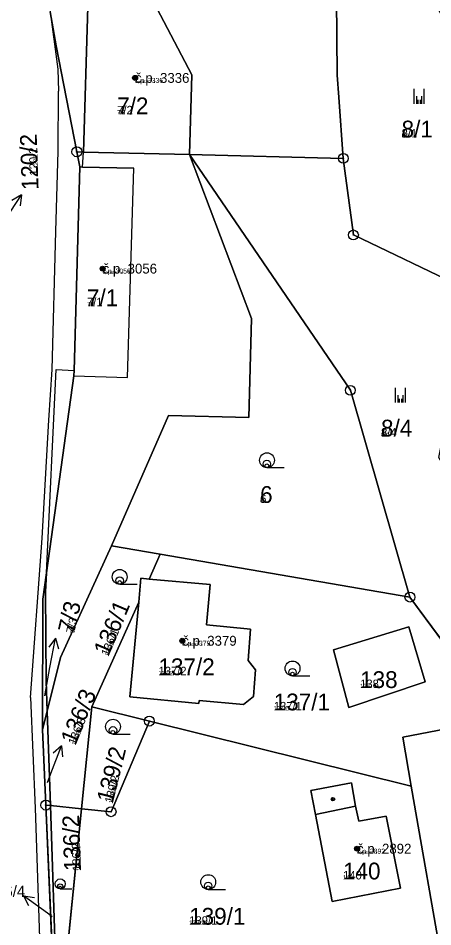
# Model space of a CAD drawing. Extents: x -759873 to -758487, y -975024 to -973516.
# Drawn here: x -759297.9 to -759256, y -974428.7 to -974336.8 of the extents above; entities that cross this region are included whole.
import ezdxf

# ---------------------------------------------------------------- set-up
doc = ezdxf.new("R2010")
doc.units = 0
for name, color, linetype in [('KAT_02_hranice parcel', 7, 'Continuous'), ('KAT_03_1000_st čísla parcelní', 7, 'Continuous'), ('KAT_03_1000_čísla parcelní', 7, 'Continuous'), ('KAT_03_1000_čísla popisná', 7, 'Continuous'), ('KAT_03_250_st čísla parcelní', 7, 'Continuous'), ('KAT_03_250_čísla parcelní', 7, 'Continuous'), ('KAT_03_250_čísla popisná', 7, 'Continuous'), ('KAT_03_500_st čísla parcelní', 7, 'Continuous'), ('KAT_03_500_čísla parcelní', 7, 'Continuous'), ('KAT_03_500_čísla popisná', 7, 'Continuous'), ('KAT_04_vnitřní kresba', 7, 'Continuous'), ('KAT_05_1000_značky kultur', 7, 'Continuous'), ('KAT_05_250_značky kultur', 7, 'Continuous'), ('KAT_05_500_značky kultur', 7, 'Continuous'), ('KAT_07_1000_značky budov', 7, 'Continuous'), ('KAT_07_250_značky budov', 7, 'Continuous'), ('KAT_07_500_značky budov', 7, 'Continuous'), ('KAT_11_značky bodu BP', 7, 'Continuous'), ('KAT_12_pomocná šipka', 7, 'Continuous'), ('KAT_14_plocha_budovy', 7, 'Continuous'), ('KAT_14_plocha_pozemek', 7, 'Continuous')]:
    doc.layers.add(name, color=color, linetype=linetype)

msp = doc.modelspace()

# ---------------------------------------------------------------- linework, layer by layer
at = {"layer": 'KAT_02_hranice parcel'}
for p, q in [((-759280.6, -974350.56), (-759265.03, -974350.94)), ((-759288.51, -974390.16), (-759283.57, -974391)), ((-759284.69, -974393.51), (-759283.57, -974391)), ((-759283.57, -974391), (-759258.29, -974395.34)), ((-759290.48, -974406.44), (-759285.74, -974395.86)), ((-759258.29, -974395.34), (-759252.87, -974402.7)), ((-759295.47, -974408.74), (-759295.01, -974406.87)), ((-759295.01, -974406.87), (-759294.68, -974416.44)), ((-759291.52, -974416.76), (-759290.48, -974406.44)), ((-759290.48, -974406.44), (-759284.66, -974407.89)), ((-759284.66, -974407.89), (-759258.17, -974414.46)), ((-759295.47, -974408.74), (-759295.14, -974416.39)), ((-759254.9, -974433.16), (-759258.17, -974414.46)), ((-759295.14, -974416.39), (-759294.12, -974439.78)), ((-759295.14, -974416.39), (-759294.68, -974416.44)), ((-759294.68, -974416.44), (-759291.52, -974416.76)), ((-759294.04, -974441.63), (-759291.52, -974416.76))]:
    msp.add_line(p, q, dxfattribs=at)
for points in [[(-759265.74, -974330.84), (-759265.67, -974342.52), (-759265.5, -974344.74), (-759265.03, -974350.94)], [(-759294.88, -974335.08), (-759294.7, -974336.11), (-759294.1, -974339.54), (-759292, -974350.28)], [(-759280.6, -974350.56), (-759280.36, -974342.49), (-759284.25, -974335.11), (-759290.88, -974335.09), (-759294.88, -974335.08)], [(-759292, -974350.28), (-759291.7, -974351.8), (-759292.28, -974372.4), (-759292.3, -974372.96), (-759295.07, -974392.89)], [(-759280.6, -974350.56), (-759291.33, -974350.3), (-759292, -974350.28)], [(-759280.6, -974350.56), (-759274.34, -974367.15), (-759274.6, -974377.18), (-759282.74, -974376.97), (-759288.51, -974390.16)], [(-759258.29, -974395.34), (-759264.32, -974374.41), (-759280.6, -974350.56)], [(-759265.03, -974350.94), (-759264.01, -974358.69), (-759252.89, -974364.02), (-759252.04, -974364.43)], [(-759295.01, -974406.87), (-759293.67, -974401.46), (-759288.51, -974390.16)], [(-759295.07, -974392.89), (-759295.44, -974395.56), (-759295.47, -974408.74)], [(-759295.07, -974392.89), (-759295.16, -974394.79), (-759295.11, -974403.85), (-759295.01, -974406.87)], [(-759284.69, -974393.51), (-759278.51, -974394.07), (-759278.88, -974398.14), (-759274.42, -974398.6), (-759274.67, -974401.75), (-759273.92, -974402.69), (-759274.11, -974405.39), (-759275.14, -974406.22), (-759279.61, -974405.79), (-759279.64, -974406.09), (-759286.64, -974405.44), (-759285.74, -974395.86)], [(-759285.74, -974395.86), (-759285.52, -974393.43), (-759284.69, -974393.51)], [(-759256.73, -974403.91), (-759264.47, -974406.51), (-759266.02, -974400.69), (-759258.4, -974398.34), (-759256.73, -974403.91)], [(-759258.17, -974414.46), (-759259, -974409.5), (-759253.74, -974408.5), (-759252.87, -974402.7)], [(-759284.66, -974407.89), (-759288.54, -974417.06), (-759291.52, -974416.76)], [(-759263.81, -974416.51), (-759263.46, -974418.01), (-759260.68, -974417.5), (-759259.23, -974424.81), (-759266.15, -974426.14), (-759267.84, -974417.34), (-759268.31, -974414.91), (-759264.21, -974414.13), (-759263.81, -974416.51)], [(-759294.68, -974416.44), (-759294.09, -974434.05), (-759294.06, -974439.07), (-759294.12, -974439.78)]]:
    msp.add_lwpolyline(points, dxfattribs=at)
at = {"layer": 'KAT_03_1000_čísla popisná'}
for centre in [(-759286.11, -974342.8), (-759289.39, -974362.1), (-759281.33, -974399.76), (-759263.64, -974420.8)]:
    msp.add_circle(centre, 0.25, dxfattribs=at)
at = {"layer": 'KAT_03_250_čísla popisná'}
for centre in [(-759286.11, -974342.8), (-759289.39, -974362.1), (-759281.33, -974399.76), (-759263.64, -974420.8)]:
    msp.add_circle(centre, 0.0625, dxfattribs=at)
at = {"layer": 'KAT_03_500_čísla popisná'}
for centre in [(-759286.11, -974342.8), (-759289.39, -974362.1), (-759281.33, -974399.76), (-759263.64, -974420.8)]:
    msp.add_circle(centre, 0.125, dxfattribs=at)
at = {"layer": 'KAT_04_vnitřní kresba'}
for p, q in [((-759294.7, -974336.11), (-759293.94, -974341.92)), ((-759291.33, -974350.3), (-759290.9, -974335.62)), ((-759293.94, -974341.92), (-759293.86, -974344.13)), ((-759293.89, -974350.2), (-759293.86, -974344.13)), ((-759294.13, -974358.35), (-759293.89, -974350.2)), ((-759291.44, -974351.83), (-759291.33, -974350.3)), ((-759291.7, -974351.8), (-759291.44, -974351.83)), ((-759291.44, -974351.83), (-759286.25, -974351.95)), ((-759286.88, -974373.11), (-759286.25, -974351.95)), ((-759294.49, -974372.3), (-759294.13, -974358.35)), ((-759295.07, -974392.89), (-759294.08, -974372.3)), ((-759294.83, -974377.45), (-759294.49, -974372.3)), ((-759294.08, -974372.3), (-759292.28, -974372.4)), ((-759292.3, -974372.96), (-759286.88, -974373.11)), ((-759295.5, -974389.38), (-759294.83, -974377.45)), ((-759296.68, -974405.49), (-759295.5, -974389.38)), ((-759296.68, -974405.49), (-759296.21, -974416.7)), ((-759296.21, -974416.7), (-759295.62, -974435.22)), ((-759267.84, -974417.34), (-759263.81, -974416.51))]:
    msp.add_line(p, q, dxfattribs=at)
at = {"layer": 'KAT_05_1000_značky kultur'}
for p, q in [((-759257.851, -974345.41), (-759257.851, -974343.91)), ((-759256.85, -974345.41), (-759256.85, -974343.91)), ((-759259.741, -974375.66), (-759259.741, -974374.16)), ((-759258.74, -974375.66), (-759258.74, -974374.16)), ((-759272.763, -974382.24), (-759271.013, -974382.24)), ((-759287.663, -974394.04), (-759285.913, -974394.04)), ((-759270.173, -974403.31), (-759268.423, -974403.31)), ((-759288.343, -974409.2), (-759286.593, -974409.2)), ((-759293.685, -974424.86), (-759292.513, -974424.86)), ((-759278.703, -974424.93), (-759276.953, -974424.93))]:
    msp.add_line(p, q, dxfattribs=at)
for centre, radius in [((-759272.763, -974381.49), 0.75), ((-759287.663, -974393.29), 0.75), ((-759270.173, -974402.56), 0.75), ((-759288.343, -974408.45), 0.75), ((-759278.703, -974424.18), 0.75), ((-759293.685, -974424.357), 0.502)]:
    msp.add_circle(centre, radius, dxfattribs=at)
at = {"layer": 'KAT_05_250_značky kultur'}
for p, q in [((-759257.468, -974345.41), (-759257.468, -974345.035)), ((-759257.218, -974345.41), (-759257.218, -974345.035)), ((-759259.358, -974375.66), (-759259.358, -974375.285)), ((-759259.108, -974375.66), (-759259.108, -974375.285)), ((-759272.768, -974382.24), (-759272.331, -974382.24)), ((-759287.668, -974394.04), (-759287.231, -974394.04)), ((-759270.178, -974403.31), (-759269.741, -974403.31)), ((-759288.348, -974409.2), (-759287.911, -974409.2)), ((-759293.689, -974424.86), (-759293.396, -974424.86)), ((-759278.708, -974424.93), (-759278.271, -974424.93))]:
    msp.add_line(p, q, dxfattribs=at)
for centre, radius in [((-759272.768, -974382.052), 0.187), ((-759287.668, -974393.852), 0.187), ((-759270.178, -974403.122), 0.187), ((-759288.348, -974409.012), 0.187), ((-759293.689, -974424.734), 0.126), ((-759278.708, -974424.742), 0.187)]:
    msp.add_circle(centre, radius, dxfattribs=at)
at = {"layer": 'KAT_05_500_značky kultur'}
for p, q in [((-759257.596, -974345.41), (-759257.596, -974344.66)), ((-759257.095, -974345.41), (-759257.095, -974344.66)), ((-759259.486, -974375.66), (-759259.486, -974374.91)), ((-759258.985, -974375.66), (-759258.985, -974374.91)), ((-759272.767, -974382.24), (-759271.892, -974382.24)), ((-759287.667, -974394.04), (-759286.792, -974394.04)), ((-759270.177, -974403.31), (-759269.302, -974403.31)), ((-759288.346, -974409.2), (-759287.471, -974409.2)), ((-759293.688, -974424.86), (-759293.101, -974424.86)), ((-759278.706, -974424.93), (-759277.831, -974424.93))]:
    msp.add_line(p, q, dxfattribs=at)
for centre, radius in [((-759272.766, -974381.865), 0.375), ((-759287.666, -974393.665), 0.375), ((-759270.176, -974402.935), 0.375), ((-759288.346, -974408.825), 0.375), ((-759293.688, -974424.609), 0.251), ((-759278.706, -974424.555), 0.375)]:
    msp.add_circle(centre, radius, dxfattribs=at)
at = {"layer": 'KAT_07_1000_značky budov'}
for centre in [(-759286.117, -974342.799), (-759289.397, -974362.099), (-759281.337, -974399.759), (-759266.077, -974415.789), (-759263.647, -974420.799)]:
    msp.add_circle(centre, 0.175, dxfattribs=at)
at = {"layer": 'KAT_07_250_značky budov'}
for centre in [(-759286.112, -974342.8), (-759289.392, -974362.1), (-759281.332, -974399.76), (-759266.072, -974415.79), (-759263.642, -974420.8)]:
    msp.add_circle(centre, 0.0437, dxfattribs=at)
at = {"layer": 'KAT_07_500_značky budov'}
for centre in [(-759286.113, -974342.8), (-759289.393, -974362.1), (-759281.333, -974399.76), (-759266.073, -974415.79), (-759263.643, -974420.8)]:
    msp.add_circle(centre, 0.0875, dxfattribs=at)
at = {"layer": 'KAT_11_značky bodu BP'}
for centre, radius in [((-759292, -974350.28), 0.5), ((-759292, -974350.28), 0.0303), ((-759265.03, -974350.94), 0.5), ((-759265.03, -974350.94), 0.0303), ((-759264.01, -974358.69), 0.5), ((-759264.01, -974358.69), 0.0303), ((-759264.32, -974374.41), 0.5), ((-759264.32, -974374.41), 0.0303), ((-759258.29, -974395.34), 0.5), ((-759258.29, -974395.34), 0.0303), ((-759284.66, -974407.89), 0.5), ((-759284.66, -974407.89), 0.0303), ((-759295.14, -974416.39), 0.5), ((-759295.14, -974416.39), 0.0303), ((-759288.54, -974417.06), 0.5), ((-759288.54, -974417.06), 0.0303)]:
    msp.add_circle(centre, radius, dxfattribs=at)
at = {"layer": 'KAT_12_pomocná šipka'}
for p, q in [((-759299.25, -974357.16), (-759297.616, -974354.643)), ((-759297.616, -974354.643), (-759298.581, -974355.21)), ((-759297.616, -974354.643), (-759297.741, -974355.756)), ((-759294.157, -974399.504), (-759294.84, -974400.392)), ((-759294.73, -974402.45), (-759294.157, -974399.504)), ((-759294.157, -974399.504), (-759293.857, -974400.583)), ((-759295.26, -974405.32), (-759294.73, -974402.45)), ((-759294.64, -974413.19), (-759293.565, -974410.388)), ((-759293.565, -974410.388), (-759294.391, -974411.144)), ((-759293.565, -974410.388), (-759293.456, -974411.503)), ((-759294.98, -974414.09), (-759294.64, -974413.19)), ((-759294.98, -974427.32), (-759297.408, -974425.556)), ((-759297.408, -974425.556), (-759296.303, -974425.74)), ((-759297.408, -974425.556), (-759296.892, -974426.55)), ((-759294.49, -974427.68), (-759294.98, -974427.32))]:
    msp.add_line(p, q, dxfattribs=at)
at = {"layer": 'KAT_14_plocha_budovy'}
for points in [[(-759280.6, -974350.56), (-759280.36, -974342.49), (-759284.25, -974335.11), (-759290.88, -974335.09), (-759290.9, -974335.62), (-759291.33, -974350.3)], [(-759292.3, -974372.96), (-759286.88, -974373.11), (-759286.25, -974351.95), (-759291.44, -974351.83), (-759291.7, -974351.8), (-759292.28, -974372.4)], [(-759279.64, -974406.09), (-759279.61, -974405.79), (-759275.14, -974406.22), (-759274.11, -974405.39), (-759273.92, -974402.69), (-759274.67, -974401.75), (-759274.42, -974398.6), (-759278.88, -974398.14), (-759278.51, -974394.07), (-759284.69, -974393.51), (-759285.52, -974393.43), (-759285.74, -974395.86), (-759286.64, -974405.44)], [(-759263.81, -974416.51), (-759267.84, -974417.34), (-759266.15, -974426.14), (-759259.23, -974424.81), (-759260.68, -974417.5), (-759263.46, -974418.01)]]:
    msp.add_lwpolyline(points, close=True, dxfattribs=at)
at = {"layer": 'KAT_14_plocha_pozemek'}
for points in [[(-759275.13, -974330.59), (-759276.47, -974329.86), (-759280.62, -974323.73), (-759282.44, -974321.04), (-759283.23, -974320.62), (-759297.93, -974312.94), (-759297.91, -974317.24), (-759297.5, -974320.18), (-759297.42, -974320.63), (-759294.88, -974335.08), (-759290.88, -974335.09), (-759284.25, -974335.11), (-759280.36, -974342.49), (-759280.6, -974350.56), (-759265.03, -974350.94), (-759265.5, -974344.74), (-759265.67, -974342.52), (-759265.74, -974330.84)], [(-759265.74, -974330.84), (-759265.67, -974342.52), (-759265.5, -974344.74), (-759265.03, -974350.94), (-759264.01, -974358.69), (-759252.89, -974364.02), (-759252.04, -974364.43), (-759251.38, -974361.09), (-759244.28, -974356.01), (-759262.85, -974322.33)], [(-759284.25, -974335.11), (-759290.88, -974335.09), (-759294.88, -974335.08), (-759294.7, -974336.11), (-759294.1, -974339.54), (-759292, -974350.28), (-759291.33, -974350.3), (-759280.6, -974350.56), (-759280.36, -974342.49)], [(-759295.11, -974403.85), (-759295.01, -974406.87), (-759293.67, -974401.46), (-759288.51, -974390.16), (-759282.74, -974376.97), (-759274.6, -974377.18), (-759274.34, -974367.15), (-759280.6, -974350.56), (-759291.33, -974350.3), (-759292, -974350.28), (-759291.7, -974351.8), (-759292.28, -974372.4), (-759292.3, -974372.96), (-759295.07, -974392.89), (-759295.16, -974394.79)], [(-759258.29, -974395.34), (-759264.32, -974374.41), (-759280.6, -974350.56), (-759274.34, -974367.15), (-759274.6, -974377.18), (-759282.74, -974376.97), (-759288.51, -974390.16), (-759283.57, -974391)], [(-759236.62, -974396.93), (-759245.48, -974393.46), (-759248.04, -974394.36), (-759249.25, -974391.99), (-759255.36, -974381.2), (-759252.04, -974364.43), (-759252.89, -974364.02), (-759264.01, -974358.69), (-759265.03, -974350.94), (-759280.6, -974350.56), (-759264.32, -974374.41), (-759258.29, -974395.34), (-759252.87, -974402.7), (-759249, -974402.07)], [(-759290.48, -974406.44), (-759285.74, -974395.86), (-759285.52, -974393.43), (-759284.69, -974393.51), (-759283.57, -974391), (-759288.51, -974390.16), (-759293.67, -974401.46), (-759295.01, -974406.87), (-759294.68, -974416.44), (-759291.52, -974416.76)], [(-759274.42, -974398.6), (-759274.67, -974401.75), (-759273.92, -974402.69), (-759274.11, -974405.39), (-759275.14, -974406.22), (-759279.61, -974405.79), (-759279.64, -974406.09), (-759286.64, -974405.44), (-759285.74, -974395.86), (-759290.48, -974406.44), (-759284.66, -974407.89), (-759258.17, -974414.46), (-759259, -974409.5), (-759253.74, -974408.5), (-759252.87, -974402.7), (-759258.29, -974395.34), (-759283.57, -974391), (-759284.69, -974393.51), (-759278.51, -974394.07), (-759278.88, -974398.14)], [(-759295.44, -974395.56), (-759295.47, -974408.74), (-759295.01, -974406.87), (-759295.11, -974403.85), (-759295.16, -974394.79), (-759295.07, -974392.89)], [(-759284.69, -974393.51), (-759285.52, -974393.43), (-759285.74, -974395.86), (-759286.64, -974405.44), (-759279.64, -974406.09), (-759279.61, -974405.79), (-759275.14, -974406.22), (-759274.11, -974405.39), (-759273.92, -974402.69), (-759274.67, -974401.75), (-759274.42, -974398.6), (-759278.88, -974398.14), (-759278.51, -974394.07)], [(-759256.73, -974403.91), (-759264.47, -974406.51), (-759266.02, -974400.69), (-759258.4, -974398.34)], [(-759256.73, -974403.91), (-759258.4, -974398.34), (-759266.02, -974400.69), (-759264.47, -974406.51)], [(-759246.94, -974406.33), (-759252.87, -974402.7), (-759253.74, -974408.5), (-759259, -974409.5), (-759258.17, -974414.46), (-759254.9, -974433.16), (-759243.31, -974423.49), (-759237.81, -974416.77), (-759240.16, -974413.72), (-759244.88, -974407.6), (-759245.61, -974407.15), (-759244.56, -974412.64), (-759248.52, -974413.4), (-759249.76, -974406.91)], [(-759295.14, -974416.39), (-759294.68, -974416.44), (-759295.01, -974406.87), (-759295.47, -974408.74)], [(-759290.48, -974406.44), (-759291.52, -974416.76), (-759288.54, -974417.06), (-759284.66, -974407.89)], [(-759284.66, -974407.89), (-759288.54, -974417.06), (-759291.52, -974416.76), (-759294.04, -974441.63), (-759271.85, -974438.8), (-759265.82, -974437.82), (-759264.14, -974436.74), (-759254.9, -974433.16), (-759258.17, -974414.46)], [(-759263.81, -974416.51), (-759263.46, -974418.01), (-759260.68, -974417.5), (-759259.23, -974424.81), (-759266.15, -974426.14), (-759267.84, -974417.34), (-759268.31, -974414.91), (-759264.21, -974414.13)], [(-759263.81, -974416.51), (-759264.21, -974414.13), (-759268.31, -974414.91), (-759267.84, -974417.34), (-759266.15, -974426.14), (-759259.23, -974424.81), (-759260.68, -974417.5), (-759263.46, -974418.01)], [(-759294.12, -974439.78), (-759294.06, -974439.07), (-759294.09, -974434.05), (-759294.68, -974416.44), (-759295.14, -974416.39)], [(-759294.06, -974439.07), (-759294.12, -974439.78), (-759294.04, -974441.63), (-759291.52, -974416.76), (-759294.68, -974416.44), (-759294.09, -974434.05)]]:
    msp.add_lwpolyline(points, close=True, dxfattribs=at)
msp.add_lwpolyline([(-759297.54, -974478.48), (-759297.23, -974474.7), (-759296.45, -974469.2), (-759296.02, -974466.22), (-759294.37, -974451.92), (-759294.21, -974448.5), (-759294.04, -974441.63), (-759294.12, -974439.78), (-759295.14, -974416.39), (-759295.47, -974408.74), (-759295.44, -974395.56), (-759295.07, -974392.89), (-759292.3, -974372.96), (-759292.28, -974372.4), (-759291.7, -974351.8), (-759292, -974350.28), (-759294.1, -974339.54), (-759294.7, -974336.11)], dxfattribs=at)

# ---------------------------------------------------------------- texts
at = {"layer": 'KAT_03_1000_st čísla parcelní'}
for s, p in [('7/2', (-759287.92, -974346.48)), ('7/1', (-759290.98, -974365.9)), ('137/2', (-759283.74, -974403.24)), ('138', (-759263.33, -974404.539)), ('140', (-759265.06, -974423.91))]:
    msp.add_text(s, height=1.7, dxfattribs=at).set_placement(p)
at = {"layer": 'KAT_03_1000_čísla parcelní'}
for s, height, p in [('8/1', 1.7, (-759259.13, -974348.83)), ('8/4', 1.7, (-759261.21, -974379.09)), ('6', 1.7, (-759273.45, -974385.809)), ('137/1', 1.7, (-759272.07, -974406.799)), ('136/4', 1.139, (-759301.038, -974425.679)), ('139/1', 1.7, (-759280.63, -974428.49))]:
    msp.add_text(s, height=height, dxfattribs=at).set_placement(p)
for s, rotation, p in [('120/2', 92, (-759295.873, -974354.122)), ('7/3', 77, (-759292.281, -974399.071)), ('136/1', 67, (-759288.807, -974401.382)), ('136/3', 68, (-759292.131, -974410.368)), ('139/2', 76, (-759288.375, -974416.255)), ('136/2', 92, (-759291.58, -974423.04))]:
    msp.add_text(s, height=1.7, rotation=rotation, dxfattribs=at).set_placement(p)
at = {"layer": 'KAT_03_1000_čísla popisná'}
for s, p in [('č.p. 3336', (-759286.11, -974343.3)), ('č.p. 3056', (-759289.39, -974362.6)), ('č.p. 3379', (-759281.33, -974400.26)), ('č.p. 2892', (-759263.64, -974421.3))]:
    msp.add_text(s, height=1, dxfattribs=at).set_placement(p)
at = {"layer": 'KAT_03_250_st čísla parcelní'}
for s, p in [('7/2', (-759287.92, -974346.48)), ('7/1', (-759290.98, -974365.9)), ('137/2', (-759283.74, -974403.24)), ('138', (-759263.33, -974404.539)), ('140', (-759265.06, -974423.91))]:
    msp.add_text(s, height=0.425, dxfattribs=at).set_placement(p)
at = {"layer": 'KAT_03_250_čísla parcelní'}
for s, p in [('8/1', (-759259.13, -974348.83)), ('8/4', (-759261.21, -974379.09)), ('6', (-759273.45, -974385.809)), ('137/1', (-759272.07, -974406.799)), ('139/1', (-759280.63, -974428.49))]:
    msp.add_text(s, height=0.425, dxfattribs=at).set_placement(p)
for s, rotation, p in [('120/2', 92, (-759295.949, -974351.943)), ('7/3', 77, (-759292.281, -974399.071)), ('136/1', 67, (-759288.807, -974401.382)), ('136/3', 68, (-759292.131, -974410.368)), ('139/2', 76, (-759288.375, -974416.255)), ('136/2', 92, (-759291.58, -974423.04))]:
    msp.add_text(s, height=0.425, rotation=rotation, dxfattribs=at).set_placement(p)
at = {"layer": 'KAT_03_250_čísla popisná'}
for s, p in [('č.p. 3336', (-759286.11, -974343.3)), ('č.p. 3056', (-759289.39, -974362.6)), ('č.p. 3379', (-759281.33, -974400.26)), ('č.p. 2892', (-759263.64, -974421.3))]:
    msp.add_text(s, height=0.25, dxfattribs=at).set_placement(p)
at = {"layer": 'KAT_03_500_st čísla parcelní'}
for s, p in [('7/2', (-759287.92, -974346.48)), ('7/1', (-759290.98, -974365.9)), ('137/2', (-759283.74, -974403.24)), ('138', (-759263.33, -974404.539)), ('140', (-759265.06, -974423.91))]:
    msp.add_text(s, height=0.85, dxfattribs=at).set_placement(p)
at = {"layer": 'KAT_03_500_čísla parcelní'}
for s, p in [('8/1', (-759259.13, -974348.83)), ('8/4', (-759261.21, -974379.09)), ('6', (-759273.45, -974385.809)), ('137/1', (-759272.07, -974406.799)), ('139/1', (-759280.63, -974428.49))]:
    msp.add_text(s, height=0.85, dxfattribs=at).set_placement(p)
for s, rotation, p in [('120/2', 92, (-759295.924, -974352.669)), ('7/3', 77, (-759292.281, -974399.071)), ('136/1', 67, (-759288.807, -974401.382)), ('136/3', 68, (-759292.131, -974410.368)), ('139/2', 76, (-759288.375, -974416.255)), ('136/2', 92, (-759291.58, -974423.04))]:
    msp.add_text(s, height=0.85, rotation=rotation, dxfattribs=at).set_placement(p)
at = {"layer": 'KAT_03_500_čísla popisná'}
for s, p in [('č.p. 3336', (-759286.11, -974343.3)), ('č.p. 3056', (-759289.39, -974362.6)), ('č.p. 3379', (-759281.33, -974400.26)), ('č.p. 2892', (-759263.64, -974421.3))]:
    msp.add_text(s, height=0.5, dxfattribs=at).set_placement(p)

doc.saveas('drawing.dxf')
